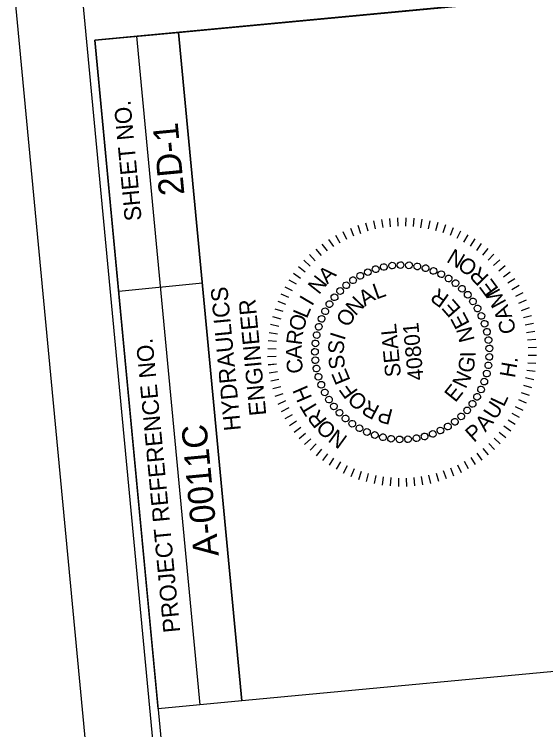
# Model space of a CAD drawing. Extents: x 554635 to 555260, y 497951 to 498841.
# Drawn here: x 554635.2 to 554714.3, y 498678.9 to 498785.5 of the extents above; entities that cross this region are included whole.
import ezdxf

# ---------------------------------------------------------------- set-up
doc = ezdxf.new("R2010")
doc.units = 0
for name, color, linetype in [('Sheet Data Field CELL', 7, 'Continuous'), ('Sheet PE Seal Cell', 7, 'Continuous'), ('Sheet Plan CELL', 7, 'Continuous'), ('Sheet Plot Border Inside CELL', 7, 'Continuous'), ('Sheet Plot Border Outside CELL', 7, 'Continuous')]:
    doc.layers.add(name, color=color, linetype=linetype)

msp = doc.modelspace()

# ---------------------------------------------------------------- linework, layer by layer
at = {"layer": 'Sheet PE Seal Cell'}
for p, q in [((554688.72, 498754.73), (554688.98, 498753.52)), ((554689.91, 498754.94), (554690.1, 498753.73)), ((554691.1, 498755.08), (554691.21, 498753.86)), ((554692.27, 498755.16), (554692.31, 498753.94)), ((554693.5, 498755.18), (554693.46, 498753.95)), ((554694.71, 498755.12), (554694.6, 498753.88)), ((554695.9, 498754.98), (554695.72, 498753.71)), ((554697.08, 498754.74), (554696.84, 498753.54)), ((554686.37, 498754.08), (554686.79, 498752.86)), ((554687.52, 498754.44), (554687.88, 498753.24)), ((554698.29, 498754.48), (554697.95, 498753.26)), ((554699.42, 498754.13), (554699.04, 498752.92)), ((554700.57, 498753.69), (554700.1, 498752.54)), ((554683.07, 498752.59), (554683.68, 498751.46)), ((554684.15, 498753.14), (554684.68, 498752.01)), ((554685.26, 498753.62), (554685.72, 498752.49)), ((554701.67, 498753.19), (554701.12, 498752.08)), ((554702.73, 498752.64), (554702.13, 498751.55)), ((554682.03, 498751.94), (554682.73, 498750.9)), ((554703.77, 498752.03), (554703.11, 498750.97)), ((554680.11, 498750.5), (554680.92, 498749.55)), ((554681.04, 498751.24), (554681.81, 498750.26)), ((554704.76, 498751.35), (554704.03, 498750.32)), ((554705.74, 498750.59), (554704.92, 498749.61)), ((554679.2, 498749.71), (554680.04, 498748.78)), ((554706.64, 498749.77), (554705.77, 498748.86)), ((554678.35, 498748.85), (554679.26, 498747.98)), ((554707.5, 498748.92), (554706.57, 498748.1)), ((554677.54, 498747.92), (554678.52, 498747.11)), ((554708.31, 498748.02), (554707.36, 498747.25)), ((554676.8, 498746.95), (554677.82, 498746.21)), ((554709.05, 498747.08), (554708.04, 498746.36)), ((554676.12, 498745.95), (554677.2, 498745.33)), ((554709.73, 498746.09), (554708.71, 498745.44)), ((554675.51, 498744.92), (554676.59, 498744.34)), ((554710.4, 498745.08), (554709.28, 498744.47)), ((554674.93, 498743.86), (554676.06, 498743.34)), ((554710.93, 498744.02), (554709.83, 498743.44)), ((554674.46, 498742.76), (554675.61, 498742.31)), ((554711.46, 498742.92), (554710.28, 498742.4)), ((554674.01, 498741.64), (554675.2, 498741.25)), ((554711.89, 498741.75), (554710.7, 498741.34)), ((554673.67, 498740.5), (554674.91, 498740.14)), ((554712.23, 498740.6), (554711.06, 498740.27)), ((554673.38, 498739.32), (554674.61, 498739.03)), ((554712.52, 498739.42), (554711.31, 498739.18)), ((554673.17, 498738.09), (554674.41, 498737.91)), ((554712.75, 498738.27), (554711.51, 498738.07)), ((554673.03, 498736.9), (554674.27, 498736.79)), ((554712.89, 498737.07), (554711.64, 498736.96)), ((554672.97, 498735.69), (554674.2, 498735.68)), ((554712.98, 498735.85), (554711.73, 498735.81)), ((554672.95, 498734.5), (554674.21, 498734.55)), ((554692.93, 498735.19), (554692.93, 498735.19)), ((554712.97, 498734.65), (554711.73, 498734.68)), ((554673.02, 498733.3), (554674.29, 498733.42)), ((554673.04, 498733.31), (554674.26, 498733.42)), ((554712.9, 498733.46), (554711.69, 498733.55)), ((554712.79, 498732.27), (554711.54, 498732.45)), ((554673.18, 498732.09), (554674.42, 498732.28)), ((554712.58, 498731.04), (554711.32, 498731.33)), ((554673.42, 498730.91), (554674.62, 498731.17)), ((554712.27, 498729.86), (554711.08, 498730.22)), ((554673.7, 498729.75), (554674.9, 498730.07)), ((554674.06, 498728.61), (554675.25, 498729.02)), ((554711.95, 498728.72), (554710.73, 498729.11)), ((554674.5, 498727.44), (554675.66, 498727.95)), ((554711, 498726.5), (554709.87, 498727.02)), ((554711.48, 498727.57), (554710.35, 498728.05)), ((554675.01, 498726.34), (554676.16, 498726.92)), ((554710.45, 498725.42), (554709.36, 498726.02)), ((554675.56, 498725.28), (554676.66, 498725.89)), ((554676.21, 498724.24), (554677.25, 498724.92)), ((554709.82, 498724.4), (554708.75, 498725.03)), ((554676.88, 498723.27), (554677.89, 498724)), ((554709.14, 498723.39), (554708.11, 498724.14)), ((554677.65, 498722.32), (554678.6, 498723.11)), ((554708.4, 498722.41), (554707.42, 498723.22)), ((554678.43, 498721.44), (554679.39, 498722.26)), ((554707.58, 498721.51), (554706.67, 498722.37)), ((554679.29, 498720.56), (554680.16, 498721.5)), ((554680.2, 498719.75), (554681.01, 498720.73)), ((554705.83, 498719.86), (554705.03, 498720.81)), ((554706.73, 498720.65), (554705.89, 498721.57)), ((554681.17, 498719.01), (554681.91, 498720.03)), ((554704.9, 498719.09), (554704.15, 498720.1)), ((554682.17, 498718.32), (554682.82, 498719.39)), ((554683.2, 498717.72), (554683.83, 498718.81)), ((554702.86, 498717.77), (554702.26, 498718.87)), ((554703.9, 498718.42), (554703.23, 498719.46)), ((554684.26, 498717.14), (554684.83, 498718.28)), ((554685.36, 498716.67), (554685.86, 498717.82)), ((554686.51, 498716.22), (554686.9, 498717.42)), ((554699.56, 498716.28), (554699.15, 498717.47)), ((554700.68, 498716.71), (554700.22, 498717.87)), ((554701.81, 498717.22), (554701.25, 498718.35)), ((554687.67, 498715.88), (554687.98, 498717.09)), ((554688.85, 498715.59), (554689.09, 498716.82)), ((554690.03, 498715.38), (554690.21, 498716.62)), ((554691.22, 498715.24), (554691.36, 498716.48)), ((554692.46, 498715.18), (554692.49, 498716.41)), ((554693.67, 498715.17), (554693.62, 498716.42)), ((554694.86, 498715.26), (554694.74, 498716.5)), ((554696.03, 498715.39), (554695.84, 498716.63)), ((554697.24, 498715.63), (554696.97, 498716.84)), ((554698.42, 498715.92), (554698.08, 498717.12))]:
    msp.add_line(p, q, dxfattribs=at)
for centre, major_axis, ratio in [((554690.24, 498747.85), (-0.102, 0.49), 0.999456), ((554691.48, 498748.06), (-0.058, 0.497), 0.999455), ((554692.73, 498748.14), (0.014, -0.5), 0.999455), ((554693.99, 498748.1), (-0.031, -0.5), 0.999457), ((554695.23, 498747.94), (-0.075, -0.495), 0.99946), ((554687.86, 498747.09), (-0.187, 0.464), 0.999463), ((554689.03, 498747.53), (-0.145, 0.479), 0.999459), ((554696.46, 498747.67), (-0.119, -0.486), 0.999465), ((554697.65, 498747.27), (-0.163, -0.473), 0.999471), ((554698.79, 498746.77), (-0.205, -0.456), 0.999478), ((554685.66, 498745.88), (-0.268, 0.423), 0.999475), ((554686.73, 498746.54), (-0.228, 0.445), 0.999468), ((554699.89, 498746.15), (-0.247, -0.435), 0.999486), ((554684.66, 498745.13), (-0.306, 0.396), 0.999482), ((554700.92, 498745.43), (-0.287, -0.41), 0.999495), ((554701.87, 498744.62), (-0.325, -0.381), 0.999504), ((554683.74, 498744.28), (-0.341, 0.366), 0.999491), ((554702.74, 498743.72), (-0.36, -0.347), 0.999512), ((554682.9, 498743.34), (-0.375, 0.332), 0.999499), ((554703.52, 498742.73), (-0.393, -0.31), 0.999521), ((554682.16, 498742.33), (-0.405, 0.294), 0.999508), ((554704.2, 498741.68), (-0.422, -0.268), 0.999528), ((554681.51, 498741.25), (-0.432, 0.253), 0.999517), ((554704.78, 498740.57), (-0.448, -0.224), 0.999535), ((554680.98, 498740.12), (-0.455, 0.208), 0.999525), ((554705.25, 498739.4), (-0.469, -0.176), 0.99954), ((554680.56, 498738.94), (-0.474, 0.161), 0.999532), ((554705.6, 498738.2), (-0.484, -0.125), 0.999544), ((554680.25, 498737.72), (-0.488, 0.111), 0.999538), ((554680.06, 498736.48), (-0.497, 0.059), 0.999542), ((554705.83, 498736.97), (-0.495, -0.073), 0.999546), ((554679.99, 498735.23), (-0.5, 0.006), 0.999545), ((554705.95, 498735.72), (0.5, 0.021), 0.999546), ((554680.05, 498733.97), (-0.498, -0.047), 0.999546), ((554705.94, 498734.46), (0.499, -0.033), 0.999544), ((554705.81, 498733.21), (0.493, -0.085), 0.99954), ((554680.22, 498732.73), (0.49, 0.1), 0.999545), ((554705.57, 498731.98), (0.482, -0.136), 0.999535), ((554680.52, 498731.51), (0.477, 0.151), 0.999542), ((554705.2, 498730.78), (0.465, -0.185), 0.999528), ((554680.93, 498730.32), (0.459, 0.2), 0.999538), ((554704.72, 498729.62), (0.444, -0.231), 0.999521), ((554681.45, 498729.18), (0.436, 0.246), 0.999532), ((554682.08, 498728.1), (0.408, 0.29), 0.999525), ((554704.13, 498728.52), (0.419, -0.274), 0.999512), ((554682.81, 498727.08), (0.377, 0.329), 0.999517), ((554702.65, 498726.5), (0.358, -0.349), 0.999495), ((554703.44, 498727.47), (0.39, -0.313), 0.999504), ((554683.64, 498726.14), (0.343, 0.365), 0.999508), ((554701.77, 498725.6), (0.324, -0.382), 0.999486), ((554684.55, 498725.28), (0.306, 0.396), 0.999499), ((554685.55, 498724.51), (0.267, 0.423), 0.999491), ((554700.81, 498724.8), (0.287, -0.41), 0.999478), ((554686.61, 498723.84), (0.226, 0.447), 0.999482), ((554687.73, 498723.28), (0.184, 0.465), 0.999475), ((554698.67, 498723.49), (0.208, -0.455), 0.999465), ((554699.77, 498724.09), (0.248, -0.435), 0.999471), ((554688.9, 498722.83), (0.141, 0.48), 0.999468), ((554690.11, 498722.49), (0.097, 0.491), 0.999463), ((554691.34, 498722.28), (0.053, 0.498), 0.999459), ((554695.1, 498722.35), (0.08, -0.494), 0.999455), ((554696.32, 498722.61), (0.124, -0.485), 0.999457), ((554697.52, 498722.99), (0.166, -0.472), 0.99946), ((554692.6, 498722.18), (0.008, 0.5), 0.999456), ((554693.85, 498722.2), (-0.036, 0.499), 0.999455)]:
    msp.add_ellipse(centre, major_axis=major_axis, ratio=ratio, dxfattribs=at)
at = {"layer": 'Sheet Plan CELL'}
for p, q in [((554669.13, 498683.22), (554659.7, 498782.8)), ((554669.13, 498683.22), (554659.7, 498782.8)), ((554662.88, 498682.63), (554653.48, 498782.21)), ((554650.79, 498744.27), (554663.23, 498745.47))]:
    msp.add_line(p, q, dxfattribs=at)
for points in [[(554647.23, 498781.63), (554717.82, 498034.95), (555240.49, 498084.36), (555169.9, 498831.04)], [(554669.13, 498683.22), (554659.7, 498782.8), (554715.71, 498788.1), (554725.14, 498688.52)], [(554656.64, 498682.04), (554647.23, 498781.63), (554659.7, 498782.8), (554669.13, 498683.22)]]:
    msp.add_lwpolyline(points, close=True, dxfattribs=at)
at = {"layer": 'Sheet Plot Border Inside CELL'}
msp.add_lwpolyline([(555248.96, 498008.08), (555170.55, 498837.37), (554645.4, 498787.73), (554723.81, 497958.43)], close=True, dxfattribs=at)
at = {"layer": 'Sheet Plot Border Outside CELL'}
msp.add_lwpolyline([(555259.53, 498002.55), (555180.3, 498840.56), (554635.23, 498789.03), (554714.46, 497951.01)], close=True, dxfattribs=at)

# ---------------------------------------------------------------- texts
at = {"layer": 'Sheet Data Field CELL'}
for s, p in [('2D-1', (554660.57, 498758.66)), ('A-0011C', (554665.69, 498704.87))]:
    msp.add_text(s, height=3.75, rotation=95.4008, dxfattribs=at).set_placement(p)
at = {"layer": 'Sheet PE Seal Cell'}
for s, height, rotation, p in [('N', 2.33, 149.427, (554702.57, 498749.54)), ('O', 2.33, 141.7382, (554704.4, 498748.12)), ('A', 2.33, 44.0578, (554681.83, 498745.22)), ('R', 2.33, 134.0493, (554706.03, 498746.47)), ('N', 2.33, 51.7467, (554680.58, 498743.64)), ('E', 2.33, 126.3604, (554707.42, 498744.61)), ('L', 2.33, 19.44, (554689.11, 498743)), ('A', 2.33, 32.7222, (554687.41, 498741.92)), ('R', 2.33, 144.4539, (554700.12, 498743.53)), ('M', 2.33, 118.6715, (554708.55, 498742.59)), ('I', 2.33, 59.4355, (554679.56, 498741.92)), ('N', 2.33, 46.0044, (554686.01, 498740.47)), ('E', 2.33, 131.1717, (554701.85, 498741.66)), ('A', 2.33, 110.9827, (554709.4, 498740.43)), ('L', 2.33, 67.1244, (554678.78, 498740.07)), ('O', 2.33, 59.2866, (554684.99, 498738.74)), ('E', 2.33, 117.8895, (554703.1, 498739.44)), ('O', 2.33, 74.8133, (554678.26, 498738.13)), ('C', 2.33, 103.2938, (554709.96, 498738.18)), ('SEAL', 2.331, 95.4008, (554692.81, 498731.57)), ('40801', 2.331, 95.4008, (554696.18, 498731.05)), ('N', 2.33, 104.6073, (554703.8, 498736.99)), ('R', 2.33, 82.5022, (554677.99, 498736.14)), ('I', 2.33, 72.5688, (554684.38, 498736.82)), ('S', 2.33, 85.851, (554684.24, 498734.81)), ('A', 2.33, 90.191, (554678, 498734.14)), ('S', 2.33, 99.1332, (554684.55, 498732.83)), ('I', 2.33, 91.3251, (554703.92, 498734.44)), ('C', 2.33, 97.8799, (554678.28, 498732.15)), ('G', 2.33, 78.0429, (554703.46, 498731.93)), ('H', 2.33, 80.1661, (554709.76, 498731.25)), ('.', 2.33, 87.855, (554710.14, 498733.54)), ('E', 2.33, 112.4154, (554685.32, 498730.97)), ('N', 2.33, 64.7606, (554702.43, 498729.6)), ('H', 2.33, 113.3187, (554679.61, 498728.36)), ('F', 2.33, 125.6976, (554686.49, 498729.33)), ('E', 2.33, 51.4784, (554700.89, 498727.57)), ('O', 2.33, 138.9798, (554688.01, 498728.01)), ('L', 2.33, 64.7274, (554708.11, 498726.91)), ('T', 2.33, 121.0076, (554680.65, 498726.64)), ('R', 2.33, 152.262, (554689.79, 498727.07)), ('U', 2.33, 57.0385, (554706.87, 498724.96)), ('R', 2.33, 128.6964, (554681.9, 498725.07)), ('P', 2.33, 165.5443, (554691.74, 498726.57)), ('O', 2.33, 136.3853, (554683.35, 498723.69)), ('A', 2.33, 49.3496, (554705.37, 498723.18)), ('P', 2.33, 41.6607, (554703.65, 498721.63)), ('N', 2.33, 144.0742, (554684.98, 498722.51))]:
    msp.add_text(s, height=height, rotation=rotation, dxfattribs=at).set_placement(p)
at = {"layer": 'Sheet Plan CELL'}
for s, p in [('SHEET NO.', (554654.2, 498754.82)), ('HYDRAULICS', (554668.97, 498723.56)), ('ENGINEER', (554672.75, 498725.8)), ('PROJECT REFERENCE NO.', (554659.94, 498693.5))]:
    msp.add_text(s, height=2.5, rotation=95.4008, dxfattribs=at).set_placement(p)

doc.saveas('drawing.dxf')
